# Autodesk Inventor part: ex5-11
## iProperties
Created: 2006-03
Part Number: ex5-11
Document SubType Name: Modeling
Designer: Elise Moss
Author: Elise Moss
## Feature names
1. Loft1
2. Shell1
3. Extrusion1
4. Sweep1
5. Extrusion2
6. Coil1
